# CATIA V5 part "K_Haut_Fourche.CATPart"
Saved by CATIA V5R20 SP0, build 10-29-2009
Part number: Haut_Fourche
Bounding box of the stored display mesh (mm): x -119.976 to 119.976, y -30 to 45.245, z -200 to 206.095
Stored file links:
  G:\Khaled_CFAO_2011\ST2M\ST2M_GR1\bmartinez\Khaled\CAD_ThinkMOTION\K_Haut_Fourche.CATPart
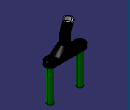
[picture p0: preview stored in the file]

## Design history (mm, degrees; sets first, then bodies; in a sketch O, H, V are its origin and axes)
Parameters
  Largeur_Fourche = 0 mm
Sketch1 on end face of Pad2, origin (0, 180, 28), H (1, 0, 0), V (0, 1, 0)
  circle A1 centre (0, -180) radius 25
  point P1 (0, -180)
  radius A1 = 25
  coincidence: P1 V
Pad1: profile Sketch1, direction (0, 0, 1), length 90
Body1 (main body)
  Sketch2 on xy-plane, origin (0, 0, 0), H (1, 0, 0), V (0, 1, 0)
    construction line L1 (-90, 0) -> (90, 0)
    line L2 (-90, 30) -> (90, 30)
    line L3 (90, -30) -> (-90, -30)
    arc A1 centre (90, 0) radius 30 from (90, 30) to (90, -30) cw
    arc A2 centre (-90, 0) radius 30 from (-90, -30) to (-90, 30) cw
    point P4 (90, 30)
    distance L1 L2 = 30
    length L2 = 180
    distance O L3 = 30
    distance V P4 = 90
    horizontal: L1 H
    tangency: A1 L2, A2 L2, A1 L3, A2 L3
  Pad2: profile Sketch2, direction (0, 0, 1), length 28
  Point1: (0, 0, 0)
  Line1: type Normal, RefPoint Point1, RefSkin yz-plane, Start 0, End 20
  Plane1: type Angle, RefPlane xy-plane, Direction Line1, Angle -15
  Line2: type Normal, RefPoint Point1, RefSkin Plane1, Start 0, End 20
  Pad3: profile end face of Pad1, direction along Line2, length 100
  DatumCurve1
  DatumCurve2
  Sketch3 on yz-plane, origin (0, 0, 0), H (0, 1, 0), V (0, 0, 1)
    line L1 (-33.9858, 235.1834) -> (-33.9858, 225.1834)
    line L2 (-33.9858, 225.1834) -> (66.2939, 198.3135)
    line L3 (66.2939, 198.3135) -> (127.7946, 235.5362)
    line L4 (127.7946, 235.5362) -> (-33.9858, 235.5362)
    point P5 (-33.9858, 235.5362)
    line L5 (-33.9858, 235.5362) -> (-33.9858, 235.1834)
    reference projected line E1 through (0, 0) direction (0.2588, 0.9659) from Line2
    length L1 = 10
    distance P5 L2 = 10
    coincidence: P5 L1
    horizontal: L4 H
    vertical: L5 V
    perpendicularity: L2 E1
  Pocket1: profile Sketch3, direction (-1, 0, 0), length 110, mirrored extent
  Point2: type Center, Curve edge [face of Pad3 | face of Pocket1 from Sketch3.L2]
  Line3: type PtDir, RefPoint Point2, Direction Line2, Start 0, End 20
  Chamfer1: length 40, angle 45, on edge [end face of Pad2 | face of Pad1 from Sketch1.A1]
  Fillet1: radius 6, on edge [face of Pad2 from Sketch2.L3 | end face of Pad2] (x2); edge [face of Pad2 from Sketch2.A2 | end face of Pad2]; edge [face of Pad2 from Sketch2.L2 | end face of Pad2] (x2); edge [face of Pad2 from Sketch2.A1 | end face of Pad2]
  Sketch4 on start face of Pad2, origin (0, 0, 0), H (1, 0, 0), V (0, -1, 0)
    circle A1 centre (-90, 0) radius 17.5
    point P1 (-90, 0)
    circle A2 centre (90, 0) radius 17.5
    point P2 (90, 0)
    radius A2 = 17.5
    radius A1 = 17.5
    distance P2 P1 = 180
  Pad4: profile Sketch4, direction (0, 0, -1), length 200 {= 200mm}
  Sketch5 on end face of Pad4, origin (0, 0, -200), H (1, 0, 0), V (0, -1, 0)
    circle A1 centre (-90, 0) radius 14
    point P1 (-90, 0)
    circle A2 centre (90, 0) radius 14
    radius A2 = 14
    radius A1 = 14
    coincidence: P1 H
  Pocket2: profile Sketch5, direction (0, 0, 1), length 80
  Fillet2: radius 6, on edge [face of Chamfer1 | face of Pad2 from Sketch2.L3]; edge [face of Chamfer1 | face of Pad2 from Sketch2.L2]
  Plane2: type Offset, RefPlane face of Pocket1 from Sketch3.L2, Offset -10, reversed
  Sketch6 on Plane2, origin (0, 51.431, 191.9433), H (1, 0, 0), V (0, -0.9659, 0.2588)
    line L1 (-90, 70) -> (80, 70)
    line L2 (80, 70) -> (80, -30)
    line L3 (80, -30) -> (-90, -30)
    line L4 (-90, -30) -> (-90, 70)
    horizontal: L1 H, L3 H
    vertical: L2 V, L4 V
  Pocket3: profile Sketch6, direction (0, 0.2588, 0.9659), length 28
  Sketch7 on start face of Pocket3, origin (0, 51.431, 191.9433), H (-1, 0, 0), V (0, -0.9659, 0.2588)
    circle A1 centre (0, 30.5406) radius 20
    reference projected curve E1 from edge [face of Pad3 | start face of Pocket3]
    radius A1 = 20
    concentricity: A1 E1
  Pocket4: profile Sketch7, direction (0, -0.2588, -0.9659), length 28
  Point3: type Center, Curve edge [start face of Pocket3 | face of Pocket4 from Sketch7.A1]
  Line4: type PtDir, RefPoint Point3, Direction Plane2, Start 0, End 20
